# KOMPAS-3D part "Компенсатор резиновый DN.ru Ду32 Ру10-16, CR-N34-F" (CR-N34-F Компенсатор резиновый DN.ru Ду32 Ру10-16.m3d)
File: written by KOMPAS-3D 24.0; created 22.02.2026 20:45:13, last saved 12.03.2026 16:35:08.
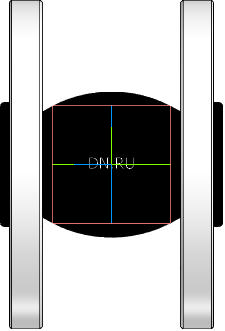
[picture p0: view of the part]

Document properties: Автор: DN.RU; Полное имя файла: CR-N34-F Компенсатор резиновый DN.ru Ду32 Ру10-16.cdw

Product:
- Body: Твердое тело2  | qty 1
    Масса: 3.844501
- Part/product: Компенсатор резиновый DN.ru Ду32 Ру10-16  | designation CR-N34-F
    Масса: 3
    Раздел спецификации: Прочие изделия
    Форматы листов документа: A3
    Комментарий: D140-02087
    Примечание: D140-02087
    additional columns: Типовые

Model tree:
1. Твердое тело2  (labels: Твердое тело2)

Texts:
  CR-N34-F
